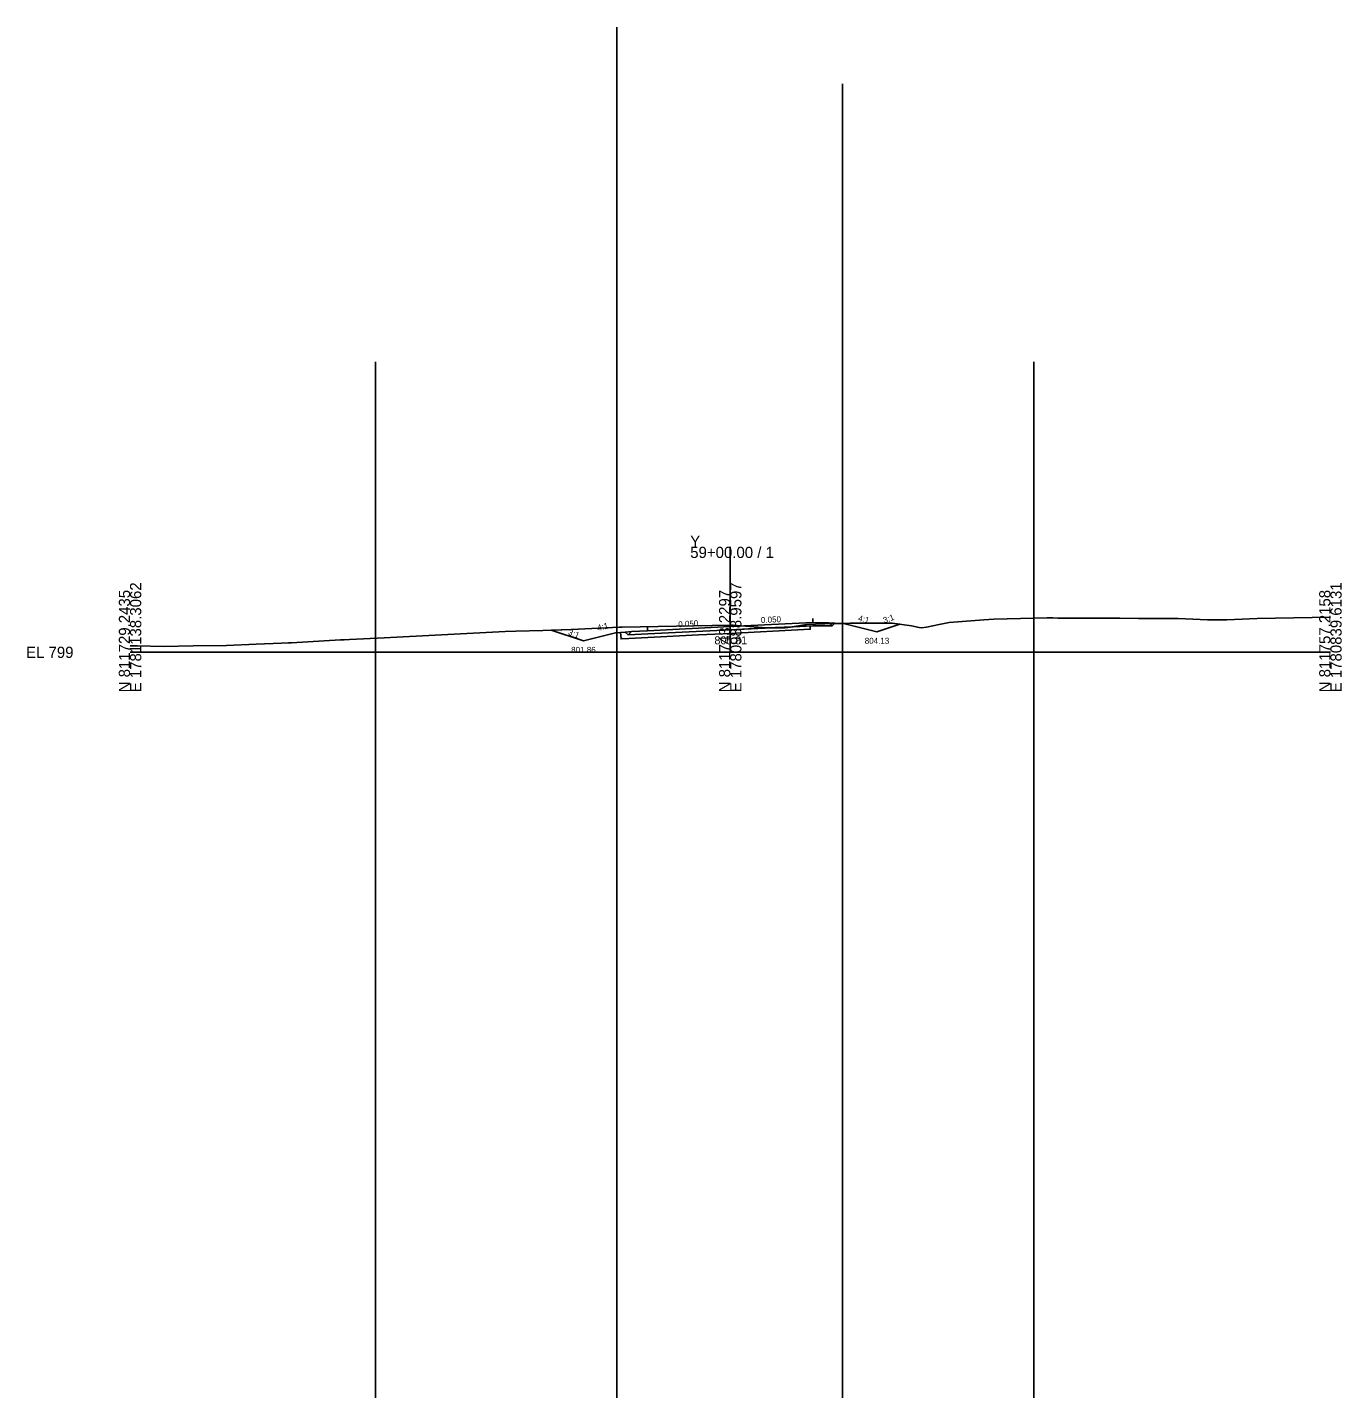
# Model space of a CAD drawing. Extents: x -12583 to 5303, y -44 to 25667.
# Drawn here: x 3974.3 to 4302.8, y 9315.9 to 9656.3 of the extents above; entities that cross this region are included whole.
import ezdxf

# ---------------------------------------------------------------- set-up
doc = ezdxf.new("R2010")
doc.units = 0
for name, color, linetype in [('Exist Cross Section Cell', 7, 'Continuous'), ('Exist XS Center Line Elevation Label', 7, 'Continuous'), ('Exist XS Ground Line', 7, 'Continuous'), ('Prop CMT Shallow Undercut', 7, 'Continuous'), ('Prop XS Ditch Slope Text', 7, 'Continuous'), ('Prop XS Ditch Standard Text', 7, 'Continuous'), ('Prop XS Dump Level', 7, 'Continuous'), ('Prop XS Earthwork Shape', 7, 'Continuous'), ('Prop XS Earthwork Undercut', 7, 'Continuous'), ('Prop XS EOT Tick Mark', 7, 'Continuous'), ('Prop XS Exc Vertical Line 1', 7, 'Continuous'), ('Prop XS Exc Vertical Line 2', 7, 'Continuous'), ('Prop XS Finish Grade', 7, 'Continuous'), ('Prop XS Finish Grade Earthwork', 7, 'Continuous'), ('Prop XS Finish Grade Paved Shoulder', 7, 'Continuous'), ('Prop XS Finish Grade Pavement', 7, 'Continuous'), ('Prop XS Pvmt Edge Slope', 7, 'Continuous'), ('Prop XS SE Text', 7, 'Continuous'), ('Prop XS Side Slope Text', 7, 'Continuous'), ('Prop XS Subgrade Earthwork', 7, 'Continuous'), ('Scratch_Level_1', 7, 'Continuous'), ('Scratch_Level_2', 7, 'Continuous'), ('Scratch_Level_3', 7, 'Continuous'), ('Scratch_Level_4', 7, 'Continuous')]:
    doc.layers.add(name, color=color, linetype=linetype)

msp = doc.modelspace()

# ---------------------------------------------------------------- linework, layer by layer
at = {"layer": 'Exist Cross Section Cell'}
for p, q in [((4150, 9500), (4150, 9526.38)), ((4000, 9500), (4150, 9500)), ((4150, 9500), (4300, 9500))]:
    msp.add_line(p, q, dxfattribs=at)
at = {"layer": 'Exist XS Ground Line'}
for p, q in [((4110.23, 9505.73), (4122.32, 9506.27)), ((4122.32, 9506.27), (4123.03, 9506.29)), ((4123.03, 9506.29), (4150, 9506.81)), ((4150, 9506.81), (4150.7, 9506.82)), ((4150.7, 9506.82), (4155.87, 9506.37)), ((4155.87, 9506.37), (4159.06, 9506.07)), ((4159.06, 9506.07), (4159.43, 9506.08)), ((4159.43, 9506.08), (4163.73, 9506.08)), ((4163.73, 9506.08), (4167.09, 9506.63)), ((4167.09, 9506.63), (4169.06, 9506.92)), ((4169.06, 9506.92), (4175.91, 9507.17)), ((4175.91, 9507.17), (4179.97, 9507.31)), ((4179.97, 9507.31), (4182.69, 9507.3)), ((4182.69, 9507.3), (4190.49, 9507.29)), ((4190.49, 9507.29), (4195.33, 9506.59)), ((4195.33, 9506.59), (4197.25, 9506.22)), ((4197.25, 9506.22), (4197.84, 9506.09)), ((4197.84, 9506.09), (4199.03, 9506.27)), ((4199.03, 9506.27), (4202.26, 9506.92)), ((4202.26, 9506.92), (4204.75, 9507.44)), ((4204.75, 9507.44), (4213.35, 9508.11)), ((4213.35, 9508.11), (4215.92, 9508.29)), ((4215.92, 9508.29), (4229.24, 9508.62)), ((4229.24, 9508.62), (4230.59, 9508.63)), ((4230.59, 9508.63), (4231.86, 9508.57)), ((4231.86, 9508.57), (4247.36, 9508.51)), ((4247.36, 9508.51), (4252.01, 9508.47)), ((4252.01, 9508.47), (4261.95, 9508.45)), ((4261.95, 9508.45), (4269.31, 9508.11)), ((4269.31, 9508.11), (4274.15, 9508.1)), ((4274.15, 9508.1), (4276.05, 9508.2)), ((4276.05, 9508.2), (4281.68, 9508.44)), ((4281.68, 9508.44), (4300, 9508.79)), ((4040.36, 9502.37), (4052.61, 9503.09)), ((4052.61, 9503.09), (4053.55, 9503.15)), ((4053.55, 9503.15), (4054.82, 9503.2)), ((4054.82, 9503.2), (4063.53, 9503.65)), ((4063.53, 9503.65), (4093.78, 9505.17)), ((4093.78, 9505.17), (4096.45, 9505.27)), ((4096.45, 9505.27), (4103.18, 9505.46)), ((4103.18, 9505.46), (4110.23, 9505.73)), ((4000, 9501.59), (4001.81, 9501.58)), ((4001.81, 9501.58), (4008.35, 9501.49)), ((4008.35, 9501.49), (4015.77, 9501.59)), ((4015.77, 9501.59), (4024.11, 9501.68)), ((4024.11, 9501.68), (4031.53, 9502.01)), ((4031.53, 9502.01), (4037.87, 9502.28)), ((4037.87, 9502.28), (4039.62, 9502.37)), ((4039.62, 9502.37), (4040.36, 9502.37))]:
    msp.add_line(p, q, dxfattribs=at)
at = {"layer": 'Prop CMT Shallow Undercut'}
msp.add_lwpolyline([(4129.37, 9504.59), (4124.49, 9504.35), (4123.78, 9505.06), (4122.58, 9504.96), (4122.71, 9503.33), (4124.69, 9503.48), (4129.38, 9503.72), (4142.1, 9504.36), (4148.2, 9504.65), (4170, 9505.75), (4170, 9506.62), (4165.73, 9506.41), (4163.73, 9506.08), (4159.43, 9506.08), (4159.06, 9506.07), (4159.03, 9506.08), (4150.04, 9505.63)], close=True, dxfattribs=at)
at = {"layer": 'Prop XS Dump Level'}
for p, q in [((4129.33, 9505.38), (4150, 9506.42)), ((4150, 9506.42), (4170.67, 9507.45))]:
    msp.add_line(p, q, dxfattribs=at)
at = {"layer": 'Prop XS Earthwork Shape'}
for points in [[(4155.87, 9506.37), (4159.03, 9506.08), (4150.04, 9505.63), (4129.37, 9504.59), (4124.49, 9504.35), (4123.78, 9505.06), (4121.33, 9504.86), (4113.33, 9502.86), (4105.29, 9505.54), (4110.23, 9505.73), (4122.32, 9506.27), (4123.03, 9506.29), (4150, 9506.81), (4150.7, 9506.82)], [(4159.06, 9506.07), (4159.43, 9506.08), (4163.73, 9506.08), (4165.73, 9506.41), (4159.03, 9506.08)], [(4165.73, 9506.41), (4167.09, 9506.63), (4169.06, 9506.92), (4175.91, 9507.17), (4176.03, 9507.17), (4175.47, 9506.61), (4170.68, 9506.66)], [(4176.03, 9507.17), (4177.38, 9507.22), (4176.16, 9507.31)], [(4186.67, 9505.13), (4192.35, 9507.02), (4190.49, 9507.29), (4182.69, 9507.3), (4179.97, 9507.31), (4177.38, 9507.22), (4178.67, 9507.13)]]:
    msp.add_lwpolyline(points, close=True, dxfattribs=at)
at = {"layer": 'Prop XS Earthwork Undercut'}
for p, q in [((4170, 9505.75), (4170, 9506.62)), ((4122.58, 9504.96), (4122.71, 9503.33)), ((4124.69, 9503.48), (4122.71, 9503.33)), ((4129.38, 9503.72), (4124.69, 9503.48)), ((4142.1, 9504.36), (4129.38, 9503.72)), ((4148.2, 9504.65), (4142.1, 9504.36)), ((4170, 9505.75), (4148.2, 9504.65))]:
    msp.add_line(p, q, dxfattribs=at)
at = {"layer": 'Prop XS EOT Tick Mark'}
for p, q in [((4129.33, 9505.38), (4129.33, 9506.38)), ((4170.67, 9507.45), (4170.67, 9508.45))]:
    msp.add_line(p, q, dxfattribs=at)
at = {"layer": 'Prop XS Exc Vertical Line 1'}
msp.add_line((4121.63, 6478.95), (4121.63, 9656.26), dxfattribs=at)
at = {"layer": 'Prop XS Exc Vertical Line 2'}
msp.add_line((4178.09, 6478.95), (4178.09, 9642.11), dxfattribs=at)
at = {"layer": 'Prop XS Finish Grade'}
for p, q in [((4174.67, 9507.41), (4176.16, 9507.31)), ((4125.33, 9505.18), (4123.78, 9505.06))]:
    msp.add_line(p, q, dxfattribs=at)
at = {"layer": 'Prop XS Finish Grade Earthwork'}
for p, q in [((4176.16, 9507.31), (4178.67, 9507.13)), ((4178.67, 9507.13), (4186.67, 9505.13)), ((4186.67, 9505.13), (4192.35, 9507.02)), ((4113.33, 9502.86), (4105.29, 9505.54)), ((4121.33, 9504.86), (4113.33, 9502.86)), ((4121.33, 9504.86), (4123.78, 9505.06))]:
    msp.add_line(p, q, dxfattribs=at)
at = {"layer": 'Prop XS Finish Grade Paved Shoulder'}
for p, q in [((4170.67, 9507.45), (4174.67, 9507.41)), ((4129.33, 9505.38), (4125.33, 9505.18))]:
    msp.add_line(p, q, dxfattribs=at)
at = {"layer": 'Prop XS Finish Grade Pavement'}
for p, q in [((4129.33, 9505.38), (4150, 9506.42)), ((4150, 9506.42), (4170.67, 9507.45))]:
    msp.add_line(p, q, dxfattribs=at)
at = {"layer": 'Prop XS Pvmt Edge Slope'}
for p, q in [((4174.67, 9507.41), (4175.47, 9506.61)), ((4125.33, 9505.18), (4124.49, 9504.35))]:
    msp.add_line(p, q, dxfattribs=at)
at = {"layer": 'Prop XS Subgrade Earthwork'}
for p, q in [((4150.04, 9505.63), (4170.68, 9506.66)), ((4170.68, 9506.66), (4175.47, 9506.61)), ((4175.47, 9506.61), (4176.16, 9507.31)), ((4124.49, 9504.35), (4123.78, 9505.06)), ((4129.37, 9504.59), (4124.49, 9504.35)), ((4129.37, 9504.59), (4150.04, 9505.63))]:
    msp.add_line(p, q, dxfattribs=at)
at = {"layer": 'Scratch_Level_1'}
msp.add_line((4061.32, 9572.59), (4061.32, 6980.12), dxfattribs=at)
at = {"layer": 'Scratch_Level_2'}
msp.add_line((4225.92, 9572.59), (4225.92, 6980.12), dxfattribs=at)
at = {"layer": 'Scratch_Level_3'}
for points in [[(4155.87, 9506.37), (4159.03, 9506.08), (4150.04, 9505.63), (4129.37, 9504.59), (4124.49, 9504.35), (4123.78, 9505.06), (4125.33, 9505.18), (4129.33, 9505.38), (4150, 9506.42), (4153.38, 9506.59)], [(4170.68, 9506.66), (4175.47, 9506.61), (4176.03, 9507.17), (4175.91, 9507.17), (4169.06, 9506.92), (4167.09, 9506.63), (4165.73, 9506.41)]]:
    msp.add_lwpolyline(points, close=True, dxfattribs=at)
at = {"layer": 'Scratch_Level_4'}
for points in [[(4129.37, 9504.59), (4124.49, 9504.35), (4123.78, 9505.06), (4121.33, 9504.86), (4113.33, 9502.86), (4105.29, 9505.54), (4110.23, 9505.73), (4122.32, 9506.27), (4123.03, 9506.29), (4150, 9506.81), (4150.7, 9506.82), (4155.87, 9506.37), (4159.03, 9506.08), (4150.04, 9505.63)], [(4167.09, 9506.63), (4169.06, 9506.92), (4175.91, 9507.17), (4176.03, 9507.17), (4175.47, 9506.61), (4170.68, 9506.66), (4165.73, 9506.41)], [(4186.67, 9505.13), (4192.35, 9507.02), (4190.49, 9507.29), (4182.69, 9507.3), (4179.97, 9507.31), (4177.38, 9507.22), (4178.67, 9507.13)]]:
    msp.add_lwpolyline(points, close=True, dxfattribs=at)

# ---------------------------------------------------------------- texts
at = {"layer": 'Exist Cross Section Cell'}
for s, p in [('Y', (4140, 9526.38)), ('59+00.00 / 1', (4140, 9523.58)), ('EL 799', (3974, 9498.6))]:
    msp.add_text(s, height=2.8, dxfattribs=at).set_placement(p)
for s, p in [('E 1781138.3062', (4002.8, 9490)), ('E 1780988.9597', (4152.8, 9490)), ('E 1780839.6131', (4302.8, 9490)), ('N 811729.2435', (4000, 9490)), ('N 811743.2297', (4150, 9490)), ('N 811757.2158', (4300, 9490))]:
    msp.add_text(s, height=2.8, rotation=90, dxfattribs=at).set_placement(p)
at = {"layer": 'Exist XS Center Line Elevation Label'}
msp.add_text('805.81', height=2, dxfattribs=at).set_placement((4146.05, 9502))
at = {"layer": 'Prop XS Ditch Slope Text'}
for rotation, p in [(14.0362, (4116.96, 9505.32)), (345.9638, (4181.86, 9507.88))]:
    msp.add_text('4:1', height=1.5, rotation=rotation, dxfattribs=at).set_placement(p)
at = {"layer": 'Prop XS Ditch Standard Text'}
for s, p in [('804.13', (4183.62, 9502.13)), ('801.86', (4110.25, 9499.86))]:
    msp.add_text(s, height=1.5, dxfattribs=at).set_placement(p)
at = {"layer": 'Prop XS Dump Level'}
for p in [(4178.67, 9507.09), (4121.33, 9504.82)]:
    msp.add_text('Case2', height=0.04, dxfattribs=at).set_placement(p)
at = {"layer": 'Prop XS SE Text'}
for p in [(4137.04, 9506.27), (4157.71, 9507.3)]:
    msp.add_text('0.050', height=1.5, rotation=2.8624, dxfattribs=at).set_placement(p)
at = {"layer": 'Prop XS Side Slope Text'}
for rotation, p in [(19.6191, (4188.51, 9507.23)), (338.2006, (4109.36, 9504.46))]:
    msp.add_text('3:1', height=1.5, rotation=rotation, dxfattribs=at).set_placement(p)

doc.saveas('drawing.dxf')
